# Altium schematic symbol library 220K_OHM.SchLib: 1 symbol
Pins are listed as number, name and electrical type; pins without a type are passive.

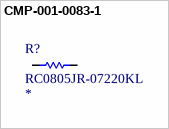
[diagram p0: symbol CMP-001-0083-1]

## CMP-001-0083-1
designator R?, comment RC0805JR-07220KL
RES SMD 220K OHM 5% 1/8W 0805; Value: 0.024inch; Value: SMD/SMT; Value: 125mW; Value: Unknown; Value: 150V; Value: -55°C; Value: 220kR; Value: 2mm; Value: No; Value: 125mW; Value: 150V; Value: 0805; Value: 155°C; Value: 2; Value: 100ppm/°C; Value: Moisture Resistant; Value: Not; Value: Tin,Matte,Lead; Value: 2012; Value: Yageo; Value: Tape and Reel; Value: Lead Free; Value: 1; Value: 1.25mm; Value: Thick Film; Value: 0.049inch; Value: 0805
footprint Resistor 0805 220000R
pins: 1, 2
